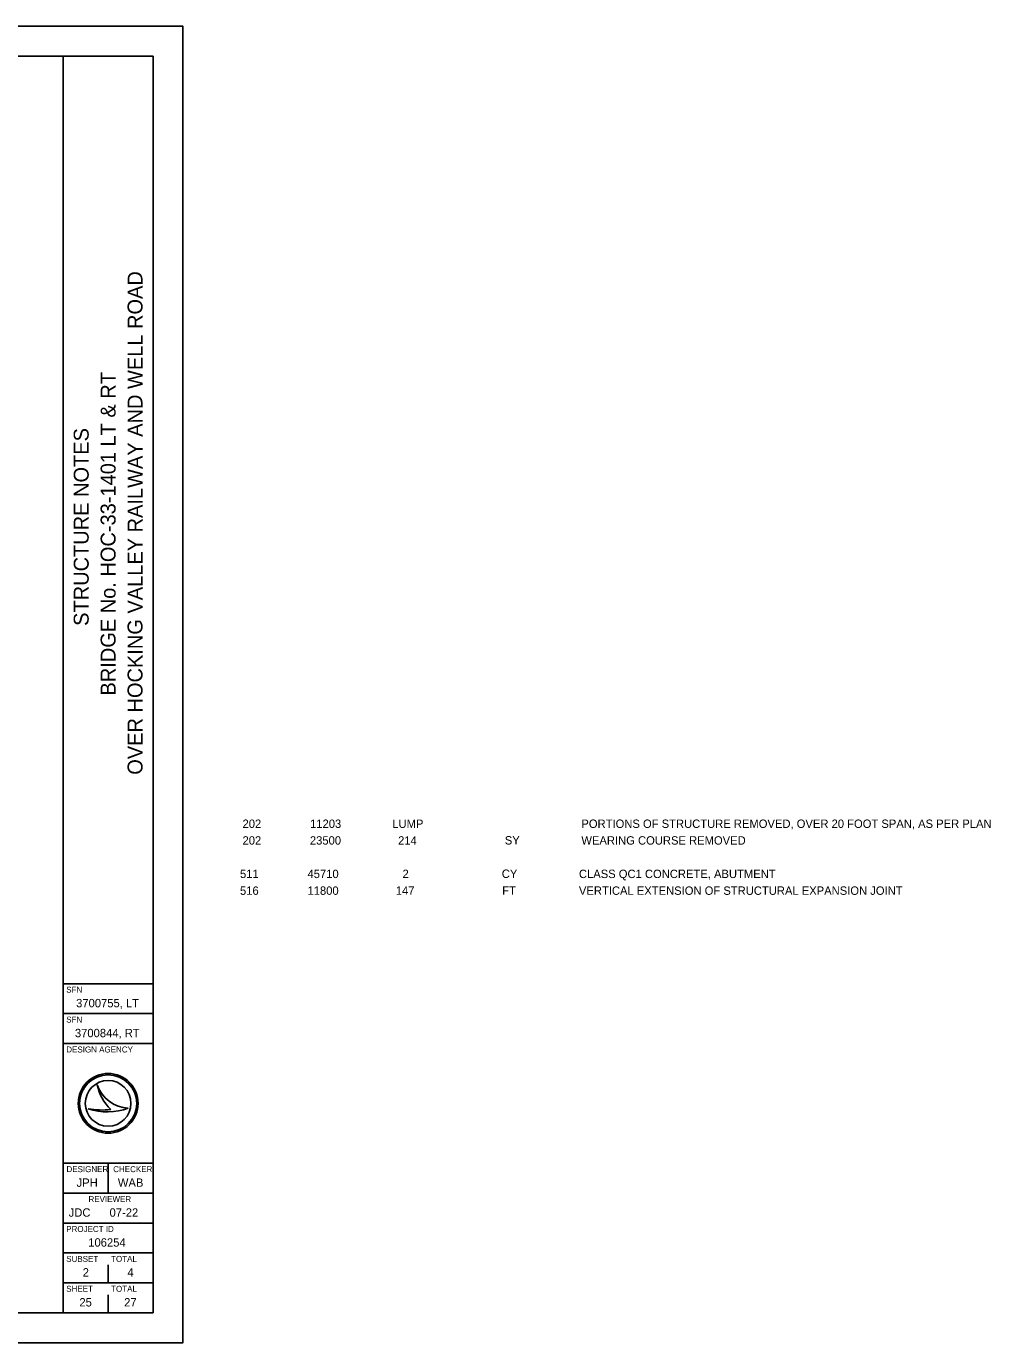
# Model space of a CAD drawing. Extents: x 0 to 47.5, y 0 to 22.
# Drawn here: x 31.38 to 47.5, y 0 to 22 of the extents above; entities that cross this region are included whole.
import ezdxf

# ---------------------------------------------------------------- set-up
doc = ezdxf.new("R2010")
doc.units = 0
for name, color, linetype in [('BR_P_Gen_Text', 7, 'Continuous'), ('SH_Border', 7, 'Continuous'), ('SH_Cut_Line', 7, 'Continuous'), ('SH_Data', 7, 'Continuous'), ('TX_P_1', 7, 'Continuous')]:
    doc.layers.add(name, color=color, linetype=linetype)

msp = doc.modelspace()

# ---------------------------------------------------------------- linework, layer by layer
at = {"layer": 'SH_Border'}
for p, q in [((32, 0.5), (32, 21.5)), ((32, 6), (33.5, 6)), ((32, 5.5), (33.5, 5.5)), ((32, 5), (33.5, 5)), ((32, 3), (33.5, 3)), ((32.75, 3), (32.75, 2.5)), ((32, 2.5), (33.5, 2.5)), ((32, 2), (33.5, 2)), ((32, 1.5), (33.5, 1.5)), ((32, 1), (33.5, 1))]:
    msp.add_line(p, q, dxfattribs=at)
msp.add_lwpolyline([(1.5, 21.5), (33.5, 21.5), (33.5, 0.5), (1.5, 0.5)], close=True, dxfattribs=at)
at = {"layer": 'SH_Cut_Line'}
msp.add_lwpolyline([(0, 0), (34, 0), (34, 22), (0, 22)], close=True, dxfattribs=at)
at = {"layer": 'SH_Data'}
for p, q in [((32.75, 5.675), (32.75, 5.675)), ((32.75, 5.175), (32.75, 5.175)), ((32.567, 4.31), (32.567, 4.31)), ((32.75, 4), (32.75, 4)), ((32.417, 3.91), (32.417, 3.91)), ((33.087, 3.919), (33.087, 3.919)), ((32.75, 1), (32.75, 1.3)), ((32.375, 0.675), (32.375, 0.675)), ((32.75, 0.5), (32.75, 0.8))]:
    msp.add_line(p, q, dxfattribs=at)
for radius in [0.5, 0.477, 0.477, 0.382]:
    msp.add_circle((32.75, 4), radius, dxfattribs=at)
for centre, radius, start, end in [((33.116, 4.498), 0.58, 198.9257, 198.9319), ((33.347, 4.47), 0.796, 191.6379, 191.6421), ((33.116, 4.498), 0.58, 198.9319, 267.1657), ((33.347, 4.47), 0.796, 191.6421, 226.0947), ((32.739, 4.87), 1.013, 251.4576, 290.0832), ((32.648, 5.154), 1.266, 259.4964, 259.4995), ((32.739, 4.87), 1.013, 251.4527, 251.4576), ((32.648, 5.154), 1.266, 259.4995, 276.6672)]:
    msp.add_arc(centre, radius, start, end, dxfattribs=at)

# ---------------------------------------------------------------- texts
at = {"layer": 'BR_P_Gen_Text'}
for s, p in [('202', (34.996, 8.603)), ('11203', (36.125, 8.603)), ('LUMP', (37.499, 8.603)), ('202', (34.996, 8.324)), ('23500', (36.122, 8.324)), ('214', (37.596, 8.324)), ('SY', (39.379, 8.326)), ('511', (34.954, 7.765)), ('45710', (36.082, 7.765)), ('2', (37.67, 7.765)), ('CY', (39.329, 7.767)), ('516', (34.954, 7.485)), ('11800', (36.082, 7.485)), ('147', (37.557, 7.485)), ('FT', (39.336, 7.487))]:
    msp.add_text(s, height=0.14, dxfattribs=at).set_placement(p)
at = {"layer": 'SH_Data'}
for s, p in [('OVER HOCKING VALLEY RAILWAY AND WELL ROAD', (33.325, 9.492)), ('BRIDGE No. HOC-33-1401 LT & RT', (32.875, 10.816)), ('STRUCTURE NOTES', (32.425, 11.98))]:
    msp.add_text(s, height=0.25, rotation=90, dxfattribs=at).set_placement(p)
for s, height, p in [('SFN', 0.1, (32.05, 5.85)), ('3700755, LT', 0.14, (32.215, 5.605)), ('SFN', 0.1, (32.05, 5.35)), ('3700844, RT', 0.14, (32.195, 5.105)), ('DESIGN AGENCY', 0.1, (32.05, 4.85)), ('DESIGNER', 0.1, (32.054, 2.85)), ('CHECKER', 0.1, (32.835, 2.85)), ('JPH', 0.14, (32.223, 2.605)), ('WAB', 0.14, (32.913, 2.605)), ('REVIEWER', 0.1, (32.422, 2.35)), ('JDC', 0.14, (32.091, 2.105)), ('07-22', 0.14, (32.774, 2.105)), ('PROJECT ID', 0.1, (32.05, 1.85)), ('106254', 0.14, (32.418, 1.605)), ('SUBSET', 0.1, (32.05, 1.35)), ('TOTAL', 0.1, (32.8, 1.35)), ('2', 0.14, (32.325, 1.105)), ('4', 0.14, (33.072, 1.105)), ('SHEET', 0.1, (32.05, 0.85)), ('TOTAL', 0.1, (32.8, 0.85)), ('25', 0.14, (32.27, 0.605)), ('27', 0.14, (33.018, 0.605))]:
    msp.add_text(s, height=height, dxfattribs=at).set_placement(p)
at = {"layer": 'TX_P_1'}
for s, p in [('PORTIONS OF STRUCTURE REMOVED, OVER 20 FOOT SPAN, AS PER PLAN', (40.659, 8.603)), ('WEARING COURSE REMOVED', (40.659, 8.324)), ('CLASS QC1 CONCRETE, ABUTMENT', (40.618, 7.765)), ('VERTICAL EXTENSION OF STRUCTURAL EXPANSION JOINT', (40.618, 7.485))]:
    msp.add_text(s, height=0.14, dxfattribs=at).set_placement(p)

doc.saveas('drawing.dxf')
